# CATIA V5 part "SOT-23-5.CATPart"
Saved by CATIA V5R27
Part number: SOT-23-5
Definition: SOT-23-5
Nomenclature: SOT-23-5 v2
Source: Unknown
Bounding box of the stored display mesh (mm): x -1.4 to 1.4, y 0 to 1.45, z -1.45 to 1.45
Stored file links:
  E:\university\my-thesis\My Thesis Publication\Final-Updata\CAD\SOT-23-5.CATPart
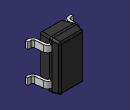
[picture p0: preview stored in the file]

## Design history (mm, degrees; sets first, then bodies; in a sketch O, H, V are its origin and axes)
Body1 "Body1" (main body)
  Solid1: solid without history
Body2 "Body2"
  Solid2: solid without history
Body3 "Body3"
  Solid3: solid without history
Body4 "Body4"
  Solid4: solid without history
Body5 "Body5"
  Solid5: solid without history
Body6 "Body6"
  Solid6: solid without history
Body7 "Body7"
  Solid7: solid without history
